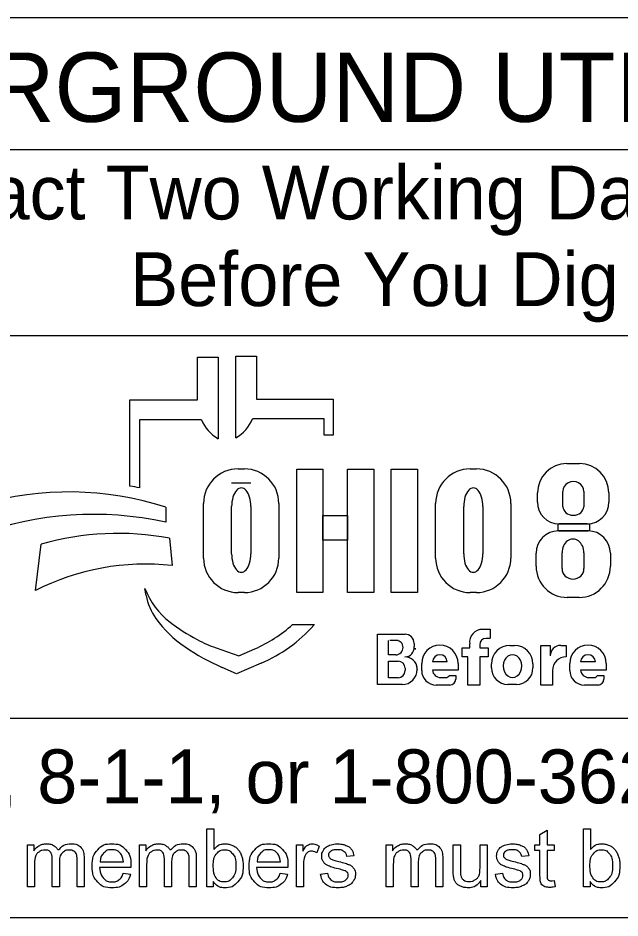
# Model space of a CAD drawing. Extents: x -1.1 to 34, y 0 to 29.8.
# Drawn here: x 3.867 to 5.431, y 2.143 to 4.48 of the extents above; entities that cross this region are included whole.
import ezdxf

# ---------------------------------------------------------------- set-up
doc = ezdxf.new("R2010")
doc.units = 0
doc.layers.add('SH_Data', color=7, linetype='Continuous')
doc.layers.add('SH_Text', color=7, linetype='Continuous')

msp = doc.modelspace()

# ---------------------------------------------------------------- linework, layer by layer
at = {"layer": 'SH_Data'}
for p, q in [((7.2275, 4.4803), (2.9775, 4.4803)), ((2.9775, 4.1387), (7.2275, 4.1387)), ((2.9775, 3.6553), (7.2275, 3.6553)), ((7.2275, 2.6607), (2.9775, 2.6607)), ((7.2275, 2.1428), (2.9775, 2.1428))]:
    msp.add_line(p, q, dxfattribs=at)
at = {"layer": 'SH_Text'}
for p, q in [((4.3335, 3.4883), (4.3335, 3.5998)), ((4.3335, 3.5998), (4.3872, 3.5998)), ((4.3872, 3.5998), (4.3872, 3.3877)), ((4.4329, 3.39), (4.4329, 3.6021)), ((4.4329, 3.6021), (4.4865, 3.6021)), ((4.4865, 3.6021), (4.4865, 3.4906)), ((4.1576, 3.2644), (4.1576, 3.4883)), ((4.1576, 3.4883), (4.3335, 3.4883)), ((4.4865, 3.4906), (4.6857, 3.4906)), ((4.6857, 3.4906), (4.6857, 3.3968)), ((4.1828, 3.4369), (4.1828, 3.26)), ((4.3439, 3.4369), (4.1828, 3.4369)), ((4.6625, 3.4392), (4.4761, 3.4392)), ((4.6625, 3.3968), (4.6625, 3.4392)), ((4.6857, 3.3968), (4.6625, 3.3968)), ((5.2931, 3.3231), (5.3258, 3.3231)), ((4.4385, 3.3091), (4.4551, 3.3091)), ((5.0416, 3.3091), (5.0581, 3.3091)), ((4.4718, 3.2721), (4.422, 3.2721)), ((5.283, 3.2111), (5.283, 3.2504)), ((5.3371, 3.2504), (5.3371, 3.2111)), ((5.2168, 3.2225), (5.2168, 3.2468)), ((5.4022, 3.2468), (5.4022, 3.2225)), ((4.2509, 3.2097), (4.2509, 3.1709)), ((4.3491, 3.0776), (4.3491, 3.2196)), ((4.422, 3.089), (4.422, 3.2114)), ((4.4718, 3.2114), (4.4718, 3.089)), ((4.5445, 3.2196), (4.5445, 3.0776)), ((4.9521, 3.0776), (4.9521, 3.2196)), ((5.025, 3.089), (5.025, 3.2114)), ((5.0748, 3.2114), (5.0748, 3.089)), ((5.1476, 3.2196), (5.1476, 3.0776)), ((5.3462, 3.1665), (5.2728, 3.1665)), ((5.271, 3.1482), (5.3483, 3.1482)), ((3.912, 2.9936), (3.9267, 3.1137)), ((4.2608, 3.1291), (4.2671, 3.0582)), ((5.2131, 3.0563), (5.2131, 3.0903)), ((5.2806, 3.0503), (5.2806, 3.0912)), ((5.3374, 3.0912), (5.3374, 3.0503)), ((5.4062, 3.0903), (5.4062, 3.0563)), ((4.1997, 2.9807), (4.1967, 2.9986)), ((4.4551, 2.9882), (4.4385, 2.9882)), ((5.0581, 2.9882), (5.0416, 2.9882)), ((5.3252, 2.9753), (5.2941, 2.9753)), ((4.58, 2.9048), (4.6375, 2.9048)), ((4.8013, 2.749), (4.8013, 2.8798)), ((4.8013, 2.8798), (4.8725, 2.8798)), ((5.0739, 2.8926), (5.0934, 2.8926)), ((5.0934, 2.8926), (5.0934, 2.8696)), ((4.8293, 2.8263), (4.8293, 2.8632)), ((4.8545, 2.8632), (4.8332, 2.8632)), ((4.8963, 2.856), (4.8963, 2.8481)), ((5.0406, 2.8442), (5.0406, 2.8546)), ((5.0667, 2.8526), (5.0667, 2.8442)), ((5.0934, 2.8691), (5.0832, 2.8691)), ((4.3816, 2.8444), (4.441, 2.8239)), ((4.441, 2.8239), (4.4821, 2.8417)), ((5.0213, 2.8212), (5.0213, 2.8442)), ((5.0213, 2.8442), (5.0406, 2.8442)), ((5.0667, 2.8442), (5.0883, 2.8442)), ((5.0883, 2.8442), (5.0883, 2.8212)), ((5.1451, 2.8508), (5.1573, 2.8508)), ((5.2254, 2.7478), (5.2254, 2.8505)), ((5.2254, 2.8505), (5.2499, 2.8505)), ((5.2499, 2.8505), (5.2499, 2.8237)), ((5.2772, 2.8505), (5.291, 2.8505)), ((5.291, 2.8505), (5.291, 2.8209)), ((4.8487, 2.8263), (4.8293, 2.8263)), ((4.8293, 2.7669), (4.8293, 2.8097)), ((4.8293, 2.8097), (4.8548, 2.8097)), ((4.9824, 2.8082), (4.9439, 2.8082)), ((5.0362, 2.8212), (5.0213, 2.8212)), ((5.0362, 2.7478), (5.0362, 2.8212)), ((5.0883, 2.8212), (5.0667, 2.8212)), ((5.0667, 2.8212), (5.0667, 2.7478)), ((5.3674, 2.8082), (5.3288, 2.8082)), ((4.435, 2.7769), (4.3976, 2.7934)), ((4.4983, 2.8044), (4.435, 2.7769)), ((4.8729, 2.7916), (4.8729, 2.7853)), ((4.9043, 2.7887), (4.9043, 2.7884)), ((4.9159, 2.7858), (4.9159, 2.8042)), ((5.0104, 2.7866), (4.944, 2.7866)), ((5.0104, 2.8042), (5.0104, 2.7866)), ((5.0973, 2.7922), (5.0973, 2.8029)), ((5.2051, 2.8029), (5.2051, 2.7922)), ((5.2559, 2.786), (5.2559, 2.7478)), ((5.3008, 2.7858), (5.3008, 2.8042)), ((5.3953, 2.7866), (5.3289, 2.7866)), ((5.3953, 2.8042), (5.3953, 2.7866)), ((4.8546, 2.7669), (4.8293, 2.7669)), ((4.9649, 2.7673), (4.979, 2.7673)), ((4.9876, 2.7729), (5.0045, 2.7729)), ((5.0045, 2.7729), (5.0045, 2.7631)), ((5.3498, 2.7673), (5.3639, 2.7673)), ((5.3725, 2.7729), (5.3894, 2.7729)), ((5.3894, 2.7729), (5.3894, 2.7631)), ((4.865, 2.749), (4.8013, 2.749)), ((4.9892, 2.7478), (4.9538, 2.7478)), ((5.0667, 2.7478), (5.0362, 2.7478)), ((5.1623, 2.7494), (5.1401, 2.7494)), ((5.2559, 2.7478), (5.2254, 2.7478)), ((5.3742, 2.7478), (5.3388, 2.7478))]:
    msp.add_line(p, q, dxfattribs=at)
for points in [[(4.591, 3.3081), (4.6589, 3.3081), (4.6589, 2.9881), (4.591, 2.9881)], [(4.7231, 3.3081), (4.7911, 3.3081), (4.7911, 2.9881), (4.7231, 2.9881)], [(4.8364, 3.3081), (4.9052, 3.3081), (4.9052, 2.9881), (4.8364, 2.9881)], [(4.6589, 3.1882), (4.7231, 3.1882), (4.7231, 3.1242), (4.6589, 3.1242)], [(5.2706, 3.1665), (5.3523, 3.1665), (5.3523, 3.1481), (5.2706, 3.1481)]]:
    msp.add_lwpolyline(points, close=True, dxfattribs=at)
for points in [[(4.3743, 2.2239), (4.3573, 2.2239), (4.3573, 2.3741), (4.3757, 2.3741), (4.3757, 2.3206)], [(5.2233, 2.2558), (5.2233, 2.3185), (5.2097, 2.3185), (5.2097, 2.3328), (5.2233, 2.3328), (5.2233, 2.3597), (5.2417, 2.3708), (5.2417, 2.3328), (5.2601, 2.3328), (5.2601, 2.3185), (5.2417, 2.3185), (5.2417, 2.2547)], [(5.3534, 2.2239), (5.3363, 2.2239), (5.3363, 2.3741), (5.3548, 2.3741), (5.3548, 2.3206)], [(3.8912, 2.2239), (3.8912, 2.3328), (3.9077, 2.3328), (3.9077, 2.3174)], [(4.1826, 2.2239), (4.1826, 2.3328), (4.1991, 2.3328), (4.1991, 2.3174)], [(4.5904, 2.2239), (4.5904, 2.3328), (4.607, 2.3328), (4.607, 2.3163)], [(4.6495, 2.3293), (4.643, 2.3122)], [(4.8236, 2.2239), (4.8236, 2.3328), (4.8401, 2.3328), (4.8401, 2.3174)], [(4.9979, 2.2654), (4.9979, 2.3328), (5.0164, 2.3328), (5.0164, 2.2724)], [(5.0676, 2.2745), (5.0676, 2.3328), (5.0861, 2.3328), (5.0861, 2.2239), (5.0696, 2.2239)], [(3.9743, 2.2871), (3.9743, 2.2239), (3.9559, 2.2239), (3.9559, 2.2946)], [(4.0388, 2.2986), (4.0388, 2.2239), (4.0203, 2.2239), (4.0203, 2.2924)], [(4.2657, 2.2871), (4.2657, 2.2239), (4.2473, 2.2239), (4.2473, 2.2946)], [(4.3301, 2.2986), (4.3301, 2.2239), (4.3117, 2.2239), (4.3117, 2.2924)], [(4.7394, 2.3046), (4.7213, 2.3022)], [(4.9067, 2.2871), (4.9067, 2.2239), (4.8883, 2.2239), (4.8883, 2.2946)], [(4.9711, 2.2986), (4.9711, 2.2239), (4.9527, 2.2239), (4.9527, 2.2924)], [(5.194, 2.3046), (5.1759, 2.3022)], [(3.9097, 2.2803), (3.9097, 2.2239), (3.8912, 2.2239)], [(4.16, 2.2736), (4.0788, 2.2736)], [(4.0799, 2.2887), (4.1406, 2.2887)], [(4.201, 2.2803), (4.201, 2.2239), (4.1826, 2.2239)], [(4.568, 2.2736), (4.4868, 2.2736)], [(4.4879, 2.2887), (4.5486, 2.2887)], [(4.6088, 2.2809), (4.6088, 2.2239), (4.5904, 2.2239)], [(4.842, 2.2803), (4.842, 2.2239), (4.8236, 2.2239)], [(4.1404, 2.2591), (4.1595, 2.2567)], [(4.5484, 2.2591), (4.5675, 2.2567)], [(4.653, 2.2564), (4.6712, 2.2593)], [(5.1076, 2.2564), (5.1258, 2.2593)], [(4.3743, 2.2375), (4.3743, 2.2239)], [(5.0696, 2.2239), (5.0696, 2.24)], [(5.2601, 2.2404), (5.2628, 2.2241)], [(5.3534, 2.2375), (5.3534, 2.2239)]]:
    msp.add_lwpolyline(points, dxfattribs=at)
for centre, radius, start, end in [((4.4353, 3.4736), 0.0985, 201.9296, 240.7469), ((4.3847, 3.476), 0.0985, 299.2531, 338.0704), ((5.2931, 3.2468), 0.0763, 90, 180), ((5.3258, 3.2468), 0.0763, 0, 90), ((4.4385, 3.2196), 0.0895, 90, 180), ((4.4551, 3.2196), 0.0895, 0, 90), ((5.0416, 3.2196), 0.0895, 90, 180), ((5.0581, 3.2196), 0.0895, 0, 90), ((3.9997, 2.4302), 0.8191, 72.1402, 106.3144), ((4.0295, 2.4554), 0.8191, 79.2074, 81.0007), ((5.2728, 3.2225), 0.056, 180, 270), ((5.3462, 3.2225), 0.056, 270, 0), ((4.0628, 2.2991), 0.8919, 77.8238, 109.8274), ((4.1267, 2.4094), 0.7322, 79.44, 105.8467), ((5.271, 3.0903), 0.0579, 90, 180), ((5.3483, 3.0903), 0.0579, 0, 90), ((4.4385, 3.0776), 0.0895, 180, 270), ((4.4551, 3.0776), 0.0895, 270, 0), ((5.0416, 3.0776), 0.0895, 180, 270), ((5.0581, 3.0776), 0.0895, 270, 0), ((4.1987, 2.4262), 0.6357, 83.8248, 116.8021), ((5.2941, 3.0563), 0.081, 180, 270), ((5.3252, 3.0563), 0.081, 270, 0), ((4.3841, 3.0707), 0.2008, 201.0457, 232.5314), ((4.341, 3.0048), 0.1433, 189.6817, 216.0884), ((4.4747, 3.1022), 0.3088, 216.0884, 235.7167), ((4.5766, 3.3219), 0.5173, 232.5314, 241.794), ((4.3387, 3.1722), 0.3602, 293.4582, 312.0712), ((4.3387, 3.1722), 0.401, 293.4582, 317.8286), ((4.8725, 2.856), 0.0238, 0, 90), ((5.0739, 2.859), 0.0335, 90, 187.5187), ((4.4914, 3.1631), 0.3371, 241.794, 250.9821), ((4.8505, 2.8463), 0.0169, 357.8325, 90), ((5.0832, 2.8526), 0.0165, 90, 180), ((4.6412, 3.3465), 0.6044, 235.7167, 246.2325), ((4.8487, 2.845), 0.0187, 270, 2.0582), ((4.8721, 2.8453), 0.0243, 270, 6.6529), ((4.8827, 2.8438), 0.0175, 347.4023, 0), ((4.9631, 2.8042), 0.0473, 0, 180), ((5.1451, 2.8029), 0.0478, 90, 180), ((5.1573, 2.8029), 0.0478, 0, 90), ((5.2768, 2.8237), 0.0269, 89.2449, 180), ((5.3481, 2.8042), 0.0473, 0, 180), ((4.8548, 2.7916), 0.0181, 0, 90), ((4.8722, 2.7889), 0.0321, 4.0748, 90), ((4.9632, 2.8072), 0.0193, 2.9632, 177.0368), ((5.2908, 2.786), 0.0349, 89.6033, 180), ((5.3481, 2.8072), 0.0193, 2.9632, 177.0368), ((4.8546, 2.7853), 0.0184, 270, 0), ((4.865, 2.7884), 0.0393, 270, 0), ((4.8714, 2.7887), 0.033, 0, 11.7502), ((4.9538, 2.7858), 0.038, 180, 270), ((4.9649, 2.7883), 0.021, 184.827, 270), ((5.1401, 2.7922), 0.0428, 180, 270), ((5.1623, 2.7922), 0.0428, 270, 0), ((5.3388, 2.7858), 0.038, 180, 270), ((5.3498, 2.7883), 0.021, 184.827, 270), ((4.979, 2.7767), 0.00938, 270, 335.9979), ((4.9892, 2.7631), 0.0152, 270, 0), ((5.3639, 2.7767), 0.00938, 270, 335.9979), ((5.3742, 2.7631), 0.0152, 270, 0)]:
    msp.add_arc(centre, radius, start, end, dxfattribs=at)
for centre, major_axis, ratio, start_param, end_param in [((5.31, 3.2504), (0.0271, 0), 0.969373, 0, 3.141593), ((4.4469, 3.2114), (0, 0.0484), 0.514403, 4.712389, 7.853982), ((5.0499, 3.2114), (0, 0.0484), 0.514403, 4.712389, 7.853982), ((5.31, 3.2111), (0.0271, 0), 0.818453, 3.141593, 6.283185), ((5.309, 3.0912), (0, 0.0358), 0.794529, 4.712389, 7.853982), ((4.4469, 3.089), (0, 0.0484), 0.514403, 1.570796, 4.712389), ((5.0499, 3.089), (0, 0.0484), 0.514403, 1.570796, 4.712389), ((5.309, 3.0503), (0.0284, 0), 0.959837, 3.141593, 6.283185), ((5.1517, 2.7976), (0, 0.029), 0.832186, 4.712389, 7.853982), ((5.1517, 2.7976), (0, 0.0302), 0.797287, 1.570796, 4.712389)]:
    msp.add_ellipse(centre, major_axis=major_axis, ratio=ratio, start_param=start_param, end_param=end_param, dxfattribs=at)
for points in [[(3.9077, 2.3174), (3.9128, 2.3254), (3.9214, 2.3303), (3.9299, 2.3352), (3.9407, 2.3352), (3.9528, 2.3352), (3.9606, 2.3301), (3.9683, 2.3251), (3.9715, 2.3161), (3.9844, 2.3352), (4.0051, 2.3352), (4.0213, 2.3352), (4.03, 2.3262), (4.0388, 2.3172), (4.0388, 2.2986)], [(3.9559, 2.2946), (3.9559, 2.3069), (3.9514, 2.313), (3.9469, 2.3191), (3.9366, 2.3191), (3.9288, 2.3191), (3.9222, 2.315), (3.9156, 2.311), (3.9126, 2.3031), (3.9097, 2.2952), (3.9097, 2.2803)], [(4.0203, 2.2924), (4.0203, 2.3035), (4.0185, 2.3083), (4.0168, 2.3132), (4.012, 2.3162), (4.0073, 2.3191), (4.001, 2.3191), (3.9895, 2.3191), (3.9819, 2.3115), (3.9743, 2.3039), (3.9743, 2.2871)], [(4.1595, 2.2567), (4.155, 2.24), (4.1428, 2.2307), (4.1306, 2.2215), (4.1117, 2.2215), (4.0878, 2.2215), (4.0738, 2.2362), (4.0598, 2.2509), (4.0598, 2.2774), (4.0598, 2.3049), (4.074, 2.32), (4.0881, 2.3352), (4.1106, 2.3352), (4.1324, 2.3352), (4.1463, 2.3203), (4.1601, 2.3055), (4.1601, 2.2785), (4.1601, 2.2769), (4.16, 2.2736)], [(4.1406, 2.2887), (4.1394, 2.3025), (4.1337, 2.3094), (4.1249, 2.3201), (4.1108, 2.3201), (4.0981, 2.3201), (4.0894, 2.3115), (4.0808, 2.303), (4.0799, 2.2887)], [(4.1991, 2.3174), (4.2042, 2.3254), (4.2127, 2.3303), (4.2212, 2.3352), (4.2321, 2.3352), (4.2442, 2.3352), (4.2519, 2.3301), (4.2597, 2.3251), (4.2628, 2.3161), (4.2758, 2.3352), (4.2965, 2.3352), (4.3127, 2.3352), (4.3214, 2.3262), (4.3301, 2.3172), (4.3301, 2.2986)], [(4.2473, 2.2946), (4.2473, 2.3069), (4.2428, 2.313), (4.2383, 2.3191), (4.228, 2.3191), (4.2202, 2.3191), (4.2136, 2.315), (4.207, 2.311), (4.204, 2.3031), (4.201, 2.2952), (4.201, 2.2803)], [(4.3117, 2.2924), (4.3117, 2.3035), (4.3099, 2.3083), (4.3081, 2.3132), (4.3034, 2.3162), (4.2987, 2.3191), (4.2923, 2.3191), (4.2809, 2.3191), (4.2733, 2.3115), (4.2657, 2.3039), (4.2657, 2.2871)], [(4.3741, 2.2792), (4.3741, 2.2596), (4.3794, 2.2509), (4.3881, 2.2366), (4.4029, 2.2366), (4.415, 2.2366), (4.4238, 2.2471), (4.4326, 2.2576), (4.4326, 2.2784), (4.4326, 2.2998), (4.4241, 2.3099), (4.4157, 2.3201), (4.4038, 2.3201), (4.3917, 2.3201), (4.3829, 2.3096), (4.3741, 2.299), (4.3741, 2.2792)], [(4.3757, 2.3206), (4.3874, 2.3352), (4.4055, 2.3352), (4.4155, 2.3352), (4.4245, 2.3311), (4.4335, 2.3271), (4.4392, 2.3198), (4.445, 2.3124), (4.4483, 2.3021), (4.4516, 2.2918), (4.4516, 2.28), (4.4516, 2.252), (4.4378, 2.2368), (4.4239, 2.2215), (4.4046, 2.2215), (4.3853, 2.2215), (4.3743, 2.2375)], [(4.5675, 2.2567), (4.563, 2.24), (4.5508, 2.2307), (4.5386, 2.2215), (4.5196, 2.2215), (4.4958, 2.2215), (4.4818, 2.2362), (4.4678, 2.2509), (4.4678, 2.2774), (4.4678, 2.3049), (4.482, 2.32), (4.4961, 2.3352), (4.5186, 2.3352), (4.5404, 2.3352), (4.5543, 2.3203), (4.5681, 2.3055), (4.5681, 2.2785), (4.5681, 2.2769), (4.568, 2.2736)], [(4.5486, 2.2887), (4.5474, 2.3025), (4.5417, 2.3094), (4.5328, 2.3201), (4.5188, 2.3201), (4.5061, 2.3201), (4.4974, 2.3115), (4.4888, 2.303), (4.4879, 2.2887)], [(4.607, 2.3163), (4.6133, 2.3278), (4.6187, 2.3315), (4.6241, 2.3352), (4.6305, 2.3352), (4.6398, 2.3352), (4.6495, 2.3293)], [(4.643, 2.3122), (4.6363, 2.3162), (4.6295, 2.3162), (4.6235, 2.3162), (4.6187, 2.3125), (4.6139, 2.3089), (4.6119, 2.3024), (4.6088, 2.2926), (4.6088, 2.2809)], [(4.7213, 2.3022), (4.7201, 2.3106), (4.7142, 2.3153), (4.7083, 2.3201), (4.6975, 2.3201), (4.6848, 2.3201), (4.6794, 2.3159), (4.6739, 2.3116), (4.6739, 2.306), (4.6739, 2.3024), (4.6762, 2.2995), (4.6785, 2.2966), (4.6833, 2.2946), (4.686, 2.2936), (4.6996, 2.2899), (4.7192, 2.2847), (4.7269, 2.2813), (4.7347, 2.278), (4.7391, 2.2717), (4.7435, 2.2653), (4.7435, 2.2559), (4.7435, 2.2467), (4.7381, 2.2386), (4.7327, 2.2304), (4.7226, 2.226), (4.7124, 2.2215), (4.6996, 2.2215), (4.6784, 2.2215), (4.6672, 2.2303), (4.6561, 2.2391), (4.653, 2.2564)], [(4.6712, 2.2593), (4.6727, 2.2483), (4.6798, 2.2425), (4.6868, 2.2366), (4.6995, 2.2366), (4.7122, 2.2366), (4.7184, 2.2418), (4.7245, 2.247), (4.7245, 2.254), (4.7245, 2.2602), (4.7191, 2.2638), (4.7153, 2.2663), (4.7002, 2.2701), (4.6799, 2.2752), (4.672, 2.2789), (4.6642, 2.2827), (4.6601, 2.2893), (4.6561, 2.2959), (4.6561, 2.3038), (4.6561, 2.3111), (4.6594, 2.3173), (4.6628, 2.3235), (4.6685, 2.3276), (4.6728, 2.3308), (4.6803, 2.333), (4.6877, 2.3352), (4.6962, 2.3352), (4.709, 2.3352), (4.7187, 2.3315), (4.7284, 2.3278), (4.733, 2.3215), (4.7377, 2.3152), (4.7394, 2.3046)], [(4.8401, 2.3174), (4.8452, 2.3254), (4.8537, 2.3303), (4.8622, 2.3352), (4.8731, 2.3352), (4.8852, 2.3352), (4.8929, 2.3301), (4.9007, 2.3251), (4.9038, 2.3161), (4.9168, 2.3352), (4.9375, 2.3352), (4.9537, 2.3352), (4.9624, 2.3262), (4.9711, 2.3172), (4.9711, 2.2986)], [(4.8883, 2.2946), (4.8883, 2.3069), (4.8838, 2.313), (4.8793, 2.3191), (4.869, 2.3191), (4.8612, 2.3191), (4.8546, 2.315), (4.848, 2.311), (4.845, 2.3031), (4.842, 2.2952), (4.842, 2.2803)], [(4.9527, 2.2924), (4.9527, 2.3035), (4.9509, 2.3083), (4.9491, 2.3132), (4.9444, 2.3162), (4.9397, 2.3191), (4.9333, 2.3191), (4.9219, 2.3191), (4.9143, 2.3115), (4.9067, 2.3039), (4.9067, 2.2871)], [(5.1759, 2.3022), (5.1747, 2.3106), (5.1688, 2.3153), (5.1629, 2.3201), (5.1521, 2.3201), (5.1394, 2.3201), (5.1339, 2.3159), (5.1285, 2.3116), (5.1285, 2.306), (5.1285, 2.3024), (5.1308, 2.2995), (5.133, 2.2966), (5.1378, 2.2946), (5.1406, 2.2936), (5.1542, 2.2899), (5.1737, 2.2847), (5.1815, 2.2813), (5.1893, 2.278), (5.1937, 2.2717), (5.1981, 2.2653), (5.1981, 2.2559), (5.1981, 2.2467), (5.1927, 2.2386), (5.1873, 2.2304), (5.1772, 2.226), (5.167, 2.2215), (5.1542, 2.2215), (5.1329, 2.2215), (5.1218, 2.2303), (5.1107, 2.2391), (5.1076, 2.2564)], [(5.1258, 2.2593), (5.1273, 2.2483), (5.1343, 2.2425), (5.1414, 2.2366), (5.154, 2.2366), (5.1668, 2.2366), (5.1729, 2.2418), (5.1791, 2.247), (5.1791, 2.254), (5.1791, 2.2602), (5.1736, 2.2638), (5.1698, 2.2663), (5.1548, 2.2701), (5.1345, 2.2752), (5.1266, 2.2789), (5.1188, 2.2827), (5.1147, 2.2893), (5.1107, 2.2959), (5.1107, 2.3038), (5.1107, 2.3111), (5.114, 2.3173), (5.1173, 2.3235), (5.1231, 2.3276), (5.1274, 2.3308), (5.1348, 2.333), (5.1423, 2.3352), (5.1508, 2.3352), (5.1636, 2.3352), (5.1733, 2.3315), (5.183, 2.3278), (5.1876, 2.3215), (5.1922, 2.3152), (5.194, 2.3046)], [(5.3532, 2.2792), (5.3532, 2.2596), (5.3585, 2.2509), (5.3672, 2.2366), (5.382, 2.2366), (5.3941, 2.2366), (5.4029, 2.2471), (5.4116, 2.2576), (5.4116, 2.2784), (5.4116, 2.2998), (5.4032, 2.3099), (5.3948, 2.3201), (5.3828, 2.3201), (5.3708, 2.3201), (5.362, 2.3096), (5.3532, 2.299), (5.3532, 2.2792)], [(5.3548, 2.3206), (5.3664, 2.3352), (5.3846, 2.3352), (5.3946, 2.3352), (5.4036, 2.3311), (5.4125, 2.3271), (5.4183, 2.3198), (5.4241, 2.3124), (5.4274, 2.3021), (5.4306, 2.2918), (5.4306, 2.28), (5.4306, 2.252), (5.4168, 2.2368), (5.403, 2.2215), (5.3836, 2.2215), (5.3644, 2.2215), (5.3534, 2.2375)], [(4.0788, 2.2736), (4.0799, 2.2557), (4.089, 2.2462), (4.0981, 2.2366), (4.1117, 2.2366), (4.1219, 2.2366), (4.1291, 2.242), (4.1362, 2.2473), (4.1404, 2.2591)], [(4.4868, 2.2736), (4.4879, 2.2557), (4.497, 2.2462), (4.5061, 2.2366), (4.5197, 2.2366), (4.5299, 2.2366), (4.537, 2.242), (4.5442, 2.2473), (4.5484, 2.2591)], [(5.0164, 2.2724), (5.0164, 2.258), (5.0175, 2.253), (5.0192, 2.2457), (5.0249, 2.2416), (5.0305, 2.2374), (5.0388, 2.2374), (5.0471, 2.2374), (5.0543, 2.2417), (5.0616, 2.2459), (5.0646, 2.2533), (5.0676, 2.2606), (5.0676, 2.2745)], [(5.0696, 2.24), (5.0569, 2.2215), (5.0351, 2.2215), (5.0255, 2.2215), (5.0171, 2.2252), (5.0088, 2.2289), (5.0047, 2.2345), (5.0007, 2.2401), (4.9991, 2.2482), (4.9979, 2.2536), (4.9979, 2.2654)], [(5.2628, 2.2241), (5.255, 2.2224), (5.2488, 2.2224), (5.2388, 2.2224), (5.2333, 2.2256), (5.2278, 2.2288), (5.2255, 2.234), (5.2233, 2.2392), (5.2233, 2.2558)], [(5.2417, 2.2547), (5.2417, 2.2468), (5.2427, 2.2445), (5.2436, 2.2423), (5.2458, 2.2409), (5.248, 2.2396), (5.2521, 2.2396), (5.2551, 2.2396), (5.2601, 2.2404)]]:
    msp.add_open_spline(points, degree=3, dxfattribs=at)

# ---------------------------------------------------------------- texts
for s, height, p in [('UNDERGROUND UTILITIES', 0.18, (3.1057, 4.2106)), ('Contact Two Working Days', 0.14, (3.3972, 3.9571)), ('Before You Dig', 0.14, (4.1583, 3.7321)), ('OHIO811, 8-1-1, or 1-800-362-2764', 0.14, (3.022, 2.4406))]:
    msp.add_text(s, height=height, dxfattribs=at).set_placement(p)

doc.saveas('drawing.dxf')
